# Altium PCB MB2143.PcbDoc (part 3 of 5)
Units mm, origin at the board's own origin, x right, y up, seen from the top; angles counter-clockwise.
Board outline 70 x 70 mm, 4 copper layers (Top Layer, Signal Layer 1, Signal Layer 2, Bottom Layer), stack 1.56 mm thick; 272 components, 188 nets, 1083 pads, 1158 vias.
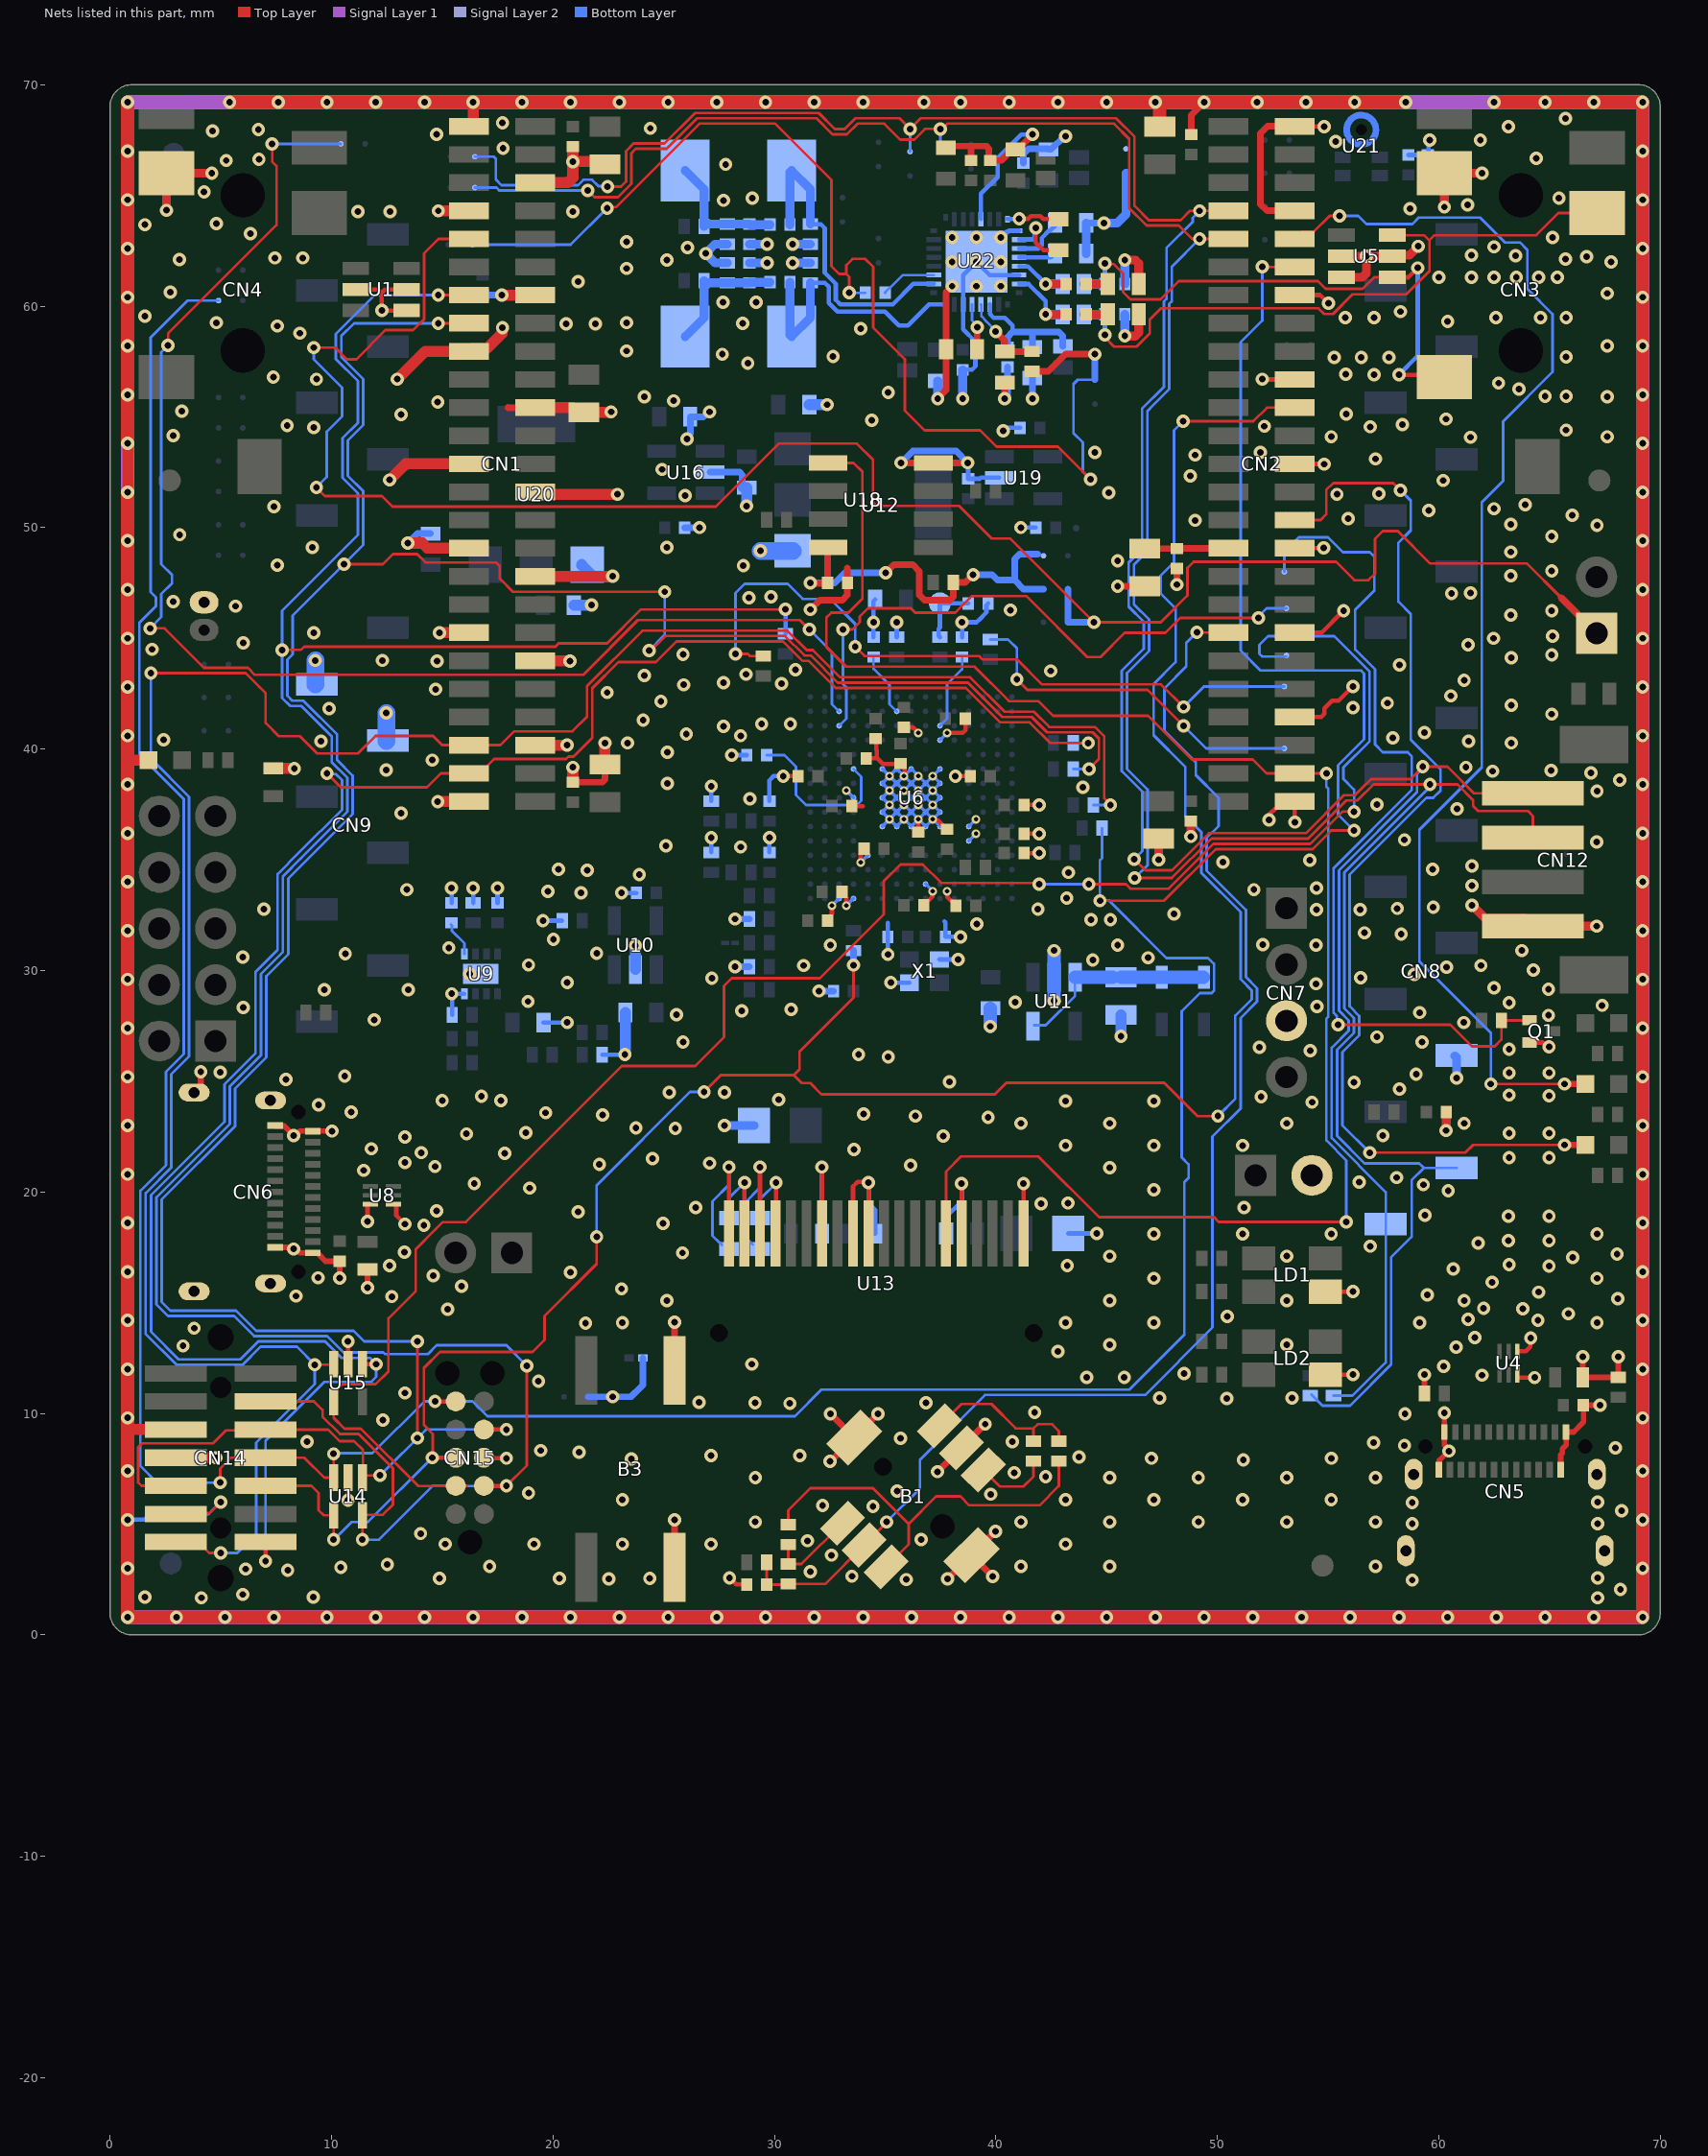
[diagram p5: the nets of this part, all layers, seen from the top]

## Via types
v1: diameter 0.6, hole 0.3, Top Layer to Bottom Layer, 1107 vias
v2: diameter 0.4, hole 0.2, Top Layer to Bottom Layer, tented both sides, 50 vias
v3: diameter 0.6, hole 0.3, Top Layer to Bottom Layer, tented both sides, 1 vias

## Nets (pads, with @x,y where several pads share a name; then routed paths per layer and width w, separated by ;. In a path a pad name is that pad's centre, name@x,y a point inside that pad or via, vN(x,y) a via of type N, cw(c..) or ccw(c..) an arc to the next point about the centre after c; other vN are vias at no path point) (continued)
GND: B1.5 B1.7 B1.8 B3.3 B3.4 C1.2 C2.1 C3.1 C4.1 C5.1 C6.1 C7.1 C8.2 C9.1 C10.1 C11.1 C13.1 C14.1 C15.1 C33.1 C34.2 C35.2 C36.1 C37.2 C38.2 C39.1 C40.2 C41.1 C42.1 C43.1 C44.1 C45.1 C46.1 C47.1 C48.1 C49.1 C50.2 C51.2 C52.2 C53.2 C54.2 C55.2 C56.2 C57.2 C58.2 C59.1 C60.1 C61.2 C62.2 C63.2 C64.2 C65.2 C66.2 C67.2 C68.2 C69.2 C70.1 C73.2 C74.2 C75.2 C76.2 C77.2 C78.2 C79.2 C80.1 C81.1 C82.1 C83.1 C84.1 C85.1 C86.1 C89.1 C90.1 C93.1 C94.1 C95.2 CN1.1 CN1.6 CN1.7 CN1.14 CN1.17 CN1.22 CN1.25 CN1.28 CN1.31 CN1.34 CN1.37 CN1.40 CN1.46 CN1.49 CN2.2 CN2.8 CN2.14 CN2.20 CN2.26 CN2.32 CN2.38 CN2.44 CN2.50 CN5.A1 CN5.A12 CN5.B1 CN5.B12 CN5.SH1 CN5.SH2 CN5.SH3 CN5.SH4 CN6.A1 CN6.A12 CN6.B1 CN6.B12 CN6.SH1 CN6.SH2 CN6.SH3 CN6.SH4 CN7.3 CN8.7 CN9.6 CN9.7 CN12.4 CN14.5 CN14.7 CN15.3 CN16.2 JP1.2 LD1.3 LD2.3 LD4.2 Q1.2 R6.1 R7.1 R11.2 R15.2 R23.2 R25.2 R27.2 R30.1 R33.2 R34.1 R40.1 R46.1 R47.1 SB1.2 SB19.2 U2.2 U3.2 U4.3 U4.4 U6.D5 U6.D6 U6.F6 U6.F7 U6.F8 U6.F9 U6.F10 U6.F12 U6.G2 U6.G6 U6.G7 U6.G8 U6.G9 U6.H6 U6.H7 U6.H8 U6.H9 U6.H10 U6.J6 U6.J7 U6.J8 U6.J9 U6.J10 U6.K6 U6.K7 U6.K8 U6.K9 U6.K10 U6.L4 U6.M1 U6.M8 U6.N1 U7.2 U8.3 U8.4 U9.8 U9.9 U10.2 U11.2 U12.4 U13.7 U13.9 U13.10 U13.16 U13.20 U14.2 U15.2 U16.2 U17.2 U18.1 U19.2 U20.1 U21.3 U22.5 X1.2 X1.4 | length 1365.4
  Top Layer w0.2: v1(10.75,6.075) U14.2@10.75,7.1 ; U15.2@10.75,12.225 v1(10.75,13.25) ; v1@11.63,18.68 U8.3@11.63,19.375 ; U8.4@12.93,19.375 12.93,18.945 v1(13.325,18.55) ; CN15.3@16.885,8 16.91,7.975 v1(17.9,7.975) ; v1(27.975,2.575) 28.275,2.275 C13.1@28.75,2.275 ; v1@30.425,38.75 30.45,38.775 C52.2@31.075,38.775 ; U13.7@32.15,18.125 v1(32.15,21.125) ; C67.2@32.4,32.35 32.4,32.375 32.6,32.575 v2(32.6,32.925) ; C66.2@33.05,33.5 33.05,33.475 33.25,33.275 v2@33.25,32.95 ; C50.2@33.5,37.425 34,37.425 ; U13.9@33.55,18.125 33.55,20.25 33.75,20.45 34.25,20.45 v1@34.275,20.425 ; v2(33.9,34.875) 33.9,35.3 C65.2@34.05,35.45 ; C53.2@34.15,39.58 34.151,39.581 34.625,39.581 ; U13.10@34.25,18.125 v1(34.25,20.425) ; C54.2@34.6,40.375 34.6,39.975 34.625,39.95 34.625,39.581 ; C55.2@35.85,40.975 36.264,40.975 36.514,40.725 v2@36.55,40.725 ; v2@35.875,38.725 35.875,39.1 35.83,39.145 35.83,39.17 35.675,39.325 34.9,39.325 34.644,39.581 34.625,39.581 ; v2@36.45,36.75 36.483,36.75 36.5,36.733 C64.2@36.5,36.25 ; C95.2@36.75,32.95 36.75,32.975 36.905,33.13 36.93,33.13 37.126,33.326 37.126,33.551 v2(37.15,33.575) ; v2(37.15,36.825) 37.187,36.788 37.387,36.788 37.62,36.555 37.62,36.53 37.775,36.375 C63.2@37.8,36.375 ; v2@37.725,33.6 37.812,33.513 37.812,33.313 38.02,33.105 38.045,33.105 38.2,32.95 C68.2@38.2,32.925 ; v2@37.825,40.7 37.85,40.725 38.5,40.725 38.625,40.85 C56.2@38.625,41.375 ; v3@38.35,38.725 38.4,38.775 C57.2@38.85,38.775 ; U13.16@38.45,18.125 v1(38.45,20.375) ; U13.20@41.25,18.125 v1(41.25,20.375) ; C62.2@41.275,35.3 41.925,35.3 v1@42,35.225 ; C61.2@41.275,36.175 41.925,36.175 v1@42,36.1 ; C58.2@41.275,37.475 v1(41.95,37.475) v1@42.025,37.4 ; v1(52.025,56.7) 52.04,56.685 CN2.20@53.5,56.685 ; v1(52.327,36.802) 52.327,37.027 52.66,37.36 53.225,37.36 CN2.50@53.5,37.635 ; CN2.50@53.48,37.635 53.5,37.615 v1(53.5,36.7) ; CN2.38@53.5,45.255 53.505,45.25 54.7,45.25 v1(55.7,46.25) ; CN2.32@53.5,49.065 53.51,49.075 v1(54.8,49.075) ; CN2.14@53.5,60.495 53.505,60.5 54.642,60.5 55.017,60.125 v1(55.025,60.125) ; CN2.2@53.5,68.115 53.504,68.111 54.809,68.111 v1(54.82,68.1) ; CN2.26@53.504,52.875 v1@54.809,52.875 ; CN2.44@53.731,41.676 CN2.44@53.5,41.445 54.695,41.445 54.841,41.591 54.841,41.841 55.175,42.175 55.475,42.175 v1(56.125,42.825) ; LD2.3@54.875,11.75 v1(56.125,11.75) ; LD1.3@54.875,15.5 v1(56.125,15.5) ; U4.3@63.628,11.625 64.32,11.625 v1(64.325,11.62) ; U4.4@63.65,12.812 63.937,12.812 64.13,13.005 64.13,13.38 v1(64.15,13.4) ; Q1.2@64.1,26.75 64.681,26.75 64.881,26.55 v1(64.975,26.55)
  Top Layer w0.25: CN6.B1@7.46,17.5 8.13,17.5 8.205,17.425 v1(8.3,17.425) 8.395,17.425 8.57,17.25 CN6.A12@9.16,17.25 9.36,17.25 9.385,17.225 9.735,16.875 C35.2@10.375,16.875 ; CN6.B12@7.46,23 7.485,22.975 7.875,22.975 v1(8.3,22.55) 8.383,22.55 8.583,22.75 CN6.A1@9.16,22.75 v1(10.025,22.75) ; v1(10.375,16.113) C35.2@10.375,16.863 ; v1(11.625,15.675) U7.2@11.625,16.5 U7.2@11.625,16.513 ; v1(11.625,18.675) v1@11.63,18.68 ; R6.1@59.35,10.9 v1(59.35,11.75) ; CN5.B12@60,7.46 60.025,7.485 60.025,7.875 v1(60.45,8.3) 60.45,8.383 60.25,8.583 CN5.A1@60.25,9.16 v1(60.25,10.025) ; CN5.B1@65.5,7.46 65.5,8.13 65.575,8.205 65.575,8.395 65.75,8.57 CN5.A12@65.75,9.16 66.085,9.16 66.537,9.613 66.537,10.375 v1(67.288,10.375) ; v1(66.505,12.555) 66.5,12.55 U2.2@66.5,11.625 R7.1@67.85,11.625 ; R7.1@68.1,11.625 68.1,12.55 v1(68.105,12.555)
  Top Layer w0.3: CN6.SH3@3.8,24.49 3.869,24.49 4.1,24.721 v1(4.1,25.425) ; 17.975,55.425 17.985,55.415 CN1.22@19.21,55.415 ; C8.2@20.9,38.5 22.225,38.5 22.35,38.625 C3.1@22.35,39.3 ; B3.3@25.5,3.05 v1(25.5,5.2) ; B3.4@25.5,11.95 v1(25.5,14.125) ; v1(31.625,46.3) 32.05,46.725 33.075,46.725 33.3,46.95 C70.1@33.3,47.5 33.3,48.175 ; v1(32.525,9.978) 32.525,9.975 B1.7@33.598,8.902 ; v1@32.538,7.841 B1.7@33.598,8.902 ; v1(34.675,9.975) 34.672,9.975 B1.7@33.598,8.902 ; v1(35.725,52.925) 35.73,52.92 U12.4@37.175,52.92 38.72,52.92 v1(38.725,52.925) ; v1(37.365,7.369) 37.369,7.369 B1.5@38.442,8.442 39.515,9.515 v1(39.519,9.515) ; C89.1@37.75,67.15 37.825,67.225 38.787,67.225 ; v1(37.825,2.525) 37.828,2.525 B1.8@38.902,3.598 ; C90.1@38.875,66.575 38.875,67.138 38.787,67.225 ; v1(39.853,2.64) 39.853,2.647 B1.8@38.902,3.598 ; v1(39.978,4.672) 39.975,4.672 B1.8@38.902,3.598 ; v1(41.65,67.75) 41.65,67.732 41.17,67.252 41.17,67.245 41,67.075 C93.1@40.875,67.075 40.75,67.075 40.25,66.575 C94.1@39.75,66.575 39.691,66.634 39.691,67.1 39.566,67.225 38.787,67.225 ; v1(45.5,47.35) C5.1@46.725,47.35 ; v1(48.175,47.425) C10.1@48.175,48.15 ; C9.1@48.815,67.745 48.815,68.615 v1(49.4,69.2) ; CN2.8@53.5,64.305 52.245,64.305 51.95,64.6 51.95,67.8 52.265,68.115 CN2.2@53.5,68.115
  Top Layer w0.4: v1(47.35,35) C6.1@47.35,35.95 ; v1(48.8,36.05) C11.1@48.8,36.75 ; v1(60.325,22.775) 60.34,22.79 C69.2@60.34,23.602 ; v1(61.5,32.95) 62.1,32.35 63.9,32.35 CN12.4@64.25,32 v1(67.125,32)
  Top Layer w0.5: 0.75,39.525 0.775,39.5 0.8,39.5 LD4.2@1.75,39.5 ; v1(0.8,9.8) 0.8,9.27 CN14.5@2.968,9.27 ; 0.8,36.975 0.825,37 ; v1(0.8,51.6) v1(0.8,53.8) ; CN14.7@2.968,8 v1(4.783,8) ; U17.2@7.375,39.125 v1(8.325,39.125) ; v1(12.625,52.15) 13.35,52.875 CN1.25@16.21,52.875 ; v1(12.975,56.7) 14.23,57.955 CN1.17@16.21,57.955 16.335,58.08 17.022,58.08 17.706,58.764 17.706,59.006 v1(17.725,59.025) ; v1@13.477,49.3 14.1,49.3 14.335,49.065 CN1.31@16.21,49.065 ; v1(14.8,37.625) 14.81,37.635 CN1.49@16.21,37.635 ; v1(14.825,64.3) 14.83,64.305 CN1.7@16.21,64.305 ; v1(14.875,45.25) 14.88,45.255 CN1.37@16.21,45.255 ; CN1.1@16.21,68.115 16.275,68.115 16.4,68.24 v1(16.4,69.2) 16.4,69.225 v1@16.425,69.25 ; v1(17.7,60.5) 17.705,60.495 CN1.14@19.21,60.495 ; CN1.34@19.186,47.795 CN1.34@19.21,47.795 22.695,47.795 v1(22.7,47.8) ; CN1.46@19.21,40.175 v1(20.645,40.175) ; CN1.40@19.21,43.985 20.765,43.985 v1(20.775,43.975) ; CN1.28@19.21,51.605 19.86,51.5 v1(22.923,51.5) ; CN1.22@19.21,55.415 20.935,55.415 21.15,55.2 C1.2@21.4,55.2 22.573,55.2 22.598,55.225 v1(22.625,55.225) ; CN1.6@19.21,65.575 20.675,65.575 20.9,65.8 v1@20.9,66.475 ; C8.2@20.9,38.5 v1(20.9,39.175) ; C7.1@20.9,67.2 v1(20.9,66.525) 22.225,66.525 C2.1@22.35,66.4 ; C3.1@22.35,39.3 v1(22.35,40.275)
  Top Layer w0.6: v1(0.8,51.6) v1(0.8,42.8) v1(0.8,40.6) 0.8,39.5 v1(0.8,29.6) v1(0.8,27.4) v1(0.8,18.6) v1(0.8,16.4) v1(0.8,7.4) v1(0.8,5.2) v1(0.8,0.8) v1(3,0.8) v1(5.2,0.8) v1(7.4,0.8) v1(16.4,0.8) v1(18.6,0.8) v1(27.4,0.8) v1(29.6,0.8) v1(40.6,0.8) v1(42.8,0.8) v1(51.6,0.8) v1(53.8,0.8) v1(62.6,0.8) v1(64.8,0.8) v1(69.2,0.8) v1(69.2,5.2) v1(69.2,7.4) v1(69.2,16.4) v1(69.2,18.6) v1(69.2,27.4) v1(69.2,29.6) v1(69.2,40.6) v1(69.2,42.8) v1(69.2,51.6) v1(69.2,53.8) v1(69.2,62.6) v1(69.2,64.8) v1(69.2,69.2) v1(67,69.2) v1(64.8,69.2) v1(62.5,69.2) ; v1(0.8,53.8) v1(0.8,62.6) v1(0.8,64.8) v1(0.8,69.2) ; v1(5.4,69.2) v1(7.6,69.2) v1(14.2,69.2) v1(16.4,69.2) v1(23,69.2) v1(25.2,69.2) v1(34,69.2) 36.2,69.2 v1(42.8,69.2) v1(45,69.2) v1(51.8,69.2) v1(54,69.2) v1(58.5,69.2) ; v1(47.2,69.2) 47.4,69 C4.1@47.4,68.1
  Signal Layer 1 w0.6: v1(58.5,69.2) v1(62.5,69.2) v1(64.8,69.2) v1(67,69.2) v1(69.2,69.2) v1(69.2,64.8) v1(69.2,62.6) v1(69.2,53.8) v1(69.2,51.6) v1(69.2,42.8) v1(69.2,40.6) v1(69.2,29.6) v1(69.2,27.4) v1(69.2,18.6) v1(69.2,16.4) v1(69.2,7.4) v1(69.2,5.2) v1(69.2,0.8) v1(64.8,0.8) v1(62.6,0.8) v1(53.8,0.8) v1(51.6,0.8) v1(42.8,0.8) v1(40.6,0.8) v1(29.6,0.8) v1(27.4,0.8) v1(18.6,0.8) v1(16.4,0.8) v1(7.4,0.8) v1(5.2,0.8) v1(0.8,0.8) v1(0.8,5.2) v1(0.8,7.4) v1(0.8,16.4) v1(0.8,18.6) v1(0.8,27.4) v1(0.8,29.6) v1(0.8,40.6) v1(0.8,42.8) v1(0.8,51.6) v1(0.8,53.8) v1(0.8,62.6) v1(0.8,64.8) v1(0.8,69.2) v1(5.4,69.2) v1(7.6,69.2) v1(14.2,69.2) v1(16.4,69.2) v1(23,69.2) v1(25.2,69.2) v1(34,69.2) 36.2,69.2 v1(42.8,69.2) v1(45,69.2) v1(51.8,69.2) v1(54,69.2) v1(56.2,69.2) v1(58.5,69.2)
  Signal Layer 2 w0.6: v1(58.5,69.2) v1(62.5,69.2) v1(64.8,69.2) v1(67,69.2) v1(69.2,69.2) v1(69.2,64.8) v1(69.2,62.6) v1(69.2,53.8) v1(69.2,51.6) v1(69.2,42.8) v1(69.2,40.6) v1(69.2,29.6) v1(69.2,27.4) v1(69.2,18.6) v1(69.2,16.4) v1(69.2,7.4) v1(69.2,5.2) v1(69.2,0.8) v1(64.8,0.8) v1(62.6,0.8) v1(53.8,0.8) v1(51.6,0.8) v1(42.8,0.8) v1(40.6,0.8) v1(29.6,0.8) v1(27.4,0.8) v1(18.6,0.8) v1(16.4,0.8) v1(7.4,0.8) v1(5.2,0.8) v1(0.8,0.8) v1(0.8,5.2) v1(0.8,7.4) v1(0.8,16.4) v1(0.8,18.6) v1(0.8,27.4) v1(0.8,29.6) v1(0.8,40.6) v1(0.8,42.8) v1(0.8,51.6) v1(0.8,53.8) v1(0.8,62.6) v1(0.8,64.8) v1(0.8,69.2) v1(5.4,69.2) v1(7.6,69.2) v1(14.2,69.2) v1(16.4,69.2) v1(23,69.2) v1(25.2,69.2) v1(34,69.2) 36.2,69.2 v1(42.8,69.2) v1(45,69.2) v1(51.8,69.2) v1(54,69.2) v1(56.2,69.2) v1(58.5,69.2)
  Bottom Layer w0.15: v2(32.6,32.925) U6.N1@32.925,33.25 ; v2(33.25,32.925) U6.M1@33.575,33.25 ; v2(33.25,38.125) U6.M8@33.575,37.8 ; v2(33.9,34.875) U6.L4@34.225,35.2 ; U6.K6@34.875,36.5 v2(35.2,36.825) ; U6.K10@34.875,39.1 v2(35.2,38.775) ; U6.G2@36.825,33.9 v2(37.15,33.575) ; U6.F6@37.475,36.5 v2(37.15,36.825) ; U6.F10@37.475,39.1 v2(37.15,38.775) ; U6.F12@37.475,40.4 v2(37.8,40.725) ; U6.D5@38.775,35.85 v2(39.1,36.175) ; U6.D6@38.775,36.5 v2(39.1,36.825) ; v2(35.2,36.825) U6.J7@35.525,37.15 ; v2(35.2,36.825) U6.J6@35.525,36.5 v2(35.85,36.825) ; v2(35.2,36.825) U6.K7@34.875,37.15 v2(35.2,37.475) ; v2(35.2,37.475) U6.J8@35.525,37.8 ; v2(35.2,37.475) U6.J7@35.525,37.15 ; v2(35.2,37.475) U6.K8@34.875,37.8 v2(35.2,38.125) ; v2(35.2,38.125) U6.J8@35.525,37.8 ; v2(35.2,38.125) U6.K9@34.875,38.45 v2(35.2,38.775) ; v2(35.2,38.125) U6.J9@35.525,38.45 ; v2(35.2,38.775) U6.J9@35.525,38.45 ; v2(35.2,38.775) U6.J10@35.525,39.1 v2(35.85,38.775) ; U6.J7@35.525,37.15 v2(35.85,36.825) ; U6.J7@35.525,37.15 v2(35.85,37.475) ; U6.J8@35.525,37.8 v2(35.85,37.475) ; U6.J8@35.525,37.8 v2(35.85,38.125) ; U6.J9@35.525,38.45 v2(35.85,38.125) ; U6.J9@35.525,38.45 v2(35.85,38.775) ; v2(35.85,36.825) U6.H7@36.175,37.15 ; v2(35.85,36.825) U6.H6@36.175,36.5 v2(36.5,36.825) ; v2(35.85,37.475) U6.H7@36.175,37.15 ; v2(35.85,37.475) U6.H8@36.175,37.8 ; v2(35.85,38.125) U6.H8@36.175,37.8 ; v2(35.85,38.125) U6.H9@36.175,38.45 ; v2(35.85,38.775) U6.H10@36.175,39.1 v2(36.5,38.775) ; v2(35.85,38.775) U6.H9@36.175,38.45 ; U6.H7@36.175,37.15 v2(36.5,36.825) ; U6.H7@36.175,37.15 v2(36.5,37.475) ; U6.H8@36.175,37.8 v2(36.5,38.125) ; U6.H8@36.175,37.8 v2(36.5,37.475) ; U6.H9@36.175,38.45 v2(36.5,38.125) ; U6.H9@36.175,38.45 v2(36.5,38.775) ; v2(36.5,36.825) U6.G6@36.825,36.5 v2(37.15,36.825) ; v2(36.5,36.825) U6.G7@36.825,37.15 ; v2(36.5,37.475) U6.G7@36.825,37.15 ; v2(36.5,37.475) U6.G8@36.825,37.8 ; v2(36.5,38.125) U6.G8@36.825,37.8 ; v2(36.5,38.125) U6.G9@36.825,38.45 ; v2(36.5,38.775) U6.G9@36.825,38.45 ; U6.G7@36.825,37.15 v2(37.15,36.825) ; U6.G7@36.825,37.15 v2(37.15,37.475) ; U6.G8@36.825,37.8 v2(37.15,37.475) ; U6.G8@36.825,37.8 v2(37.15,38.125) ; U6.G9@36.825,38.45 v2(37.15,38.775) ; U6.G9@36.825,38.45 v2(37.15,38.125) ; v2(37.15,36.825) U6.F7@37.475,37.15 v2(37.15,37.475) ; v2(37.15,37.475) U6.F8@37.475,37.8 v2(37.15,38.125) ; v2(37.15,38.125) U6.F9@37.475,38.45 v2(37.15,38.775)
  Bottom Layer w0.2: v1@0.7,5.2 v1(0.8,5.2) 1.575,5.2 1.835,5.46 R47.1@2.518,5.46 ; v1@15.4,28.95 15.45,28.9 R33.2@15.45,27.995 ; C45.1@15.425,33.05 v1(15.425,33.725) ; v1(15.43,28.95) U9.8@16,28.95 ; v1(16.25,29.85) U9.9@16.75,29.85 ; R34.1@16.4,33.05 v1(16.4,33.725) ; C44.1@17.5,33.05 v1(17.5,33.725) ; v1(19.55,32.25) R40.1@20.42,32.25 ; C43.1@19.575,27.645 20.645,27.645 v1(20.65,27.65) ; R30.1@22.225,26.195 23.245,26.195 v1(23.25,26.2) ; v1(23.1,33.5) C46.1@23.775,33.5 ; v1@23.2,26.2 v1@23.275,26.275 ; R11.2@27.15,35.33 v1(27.15,36.005) ; R15.2@27.15,37.65 v1(27.15,38.325) ; v1(28.075,39.725) C48.1@28.75,39.725 ; C37.2@29.775,35.33 v1(29.775,36.005) ; C38.2@29.775,37.65 29.775,38.575 29.975,38.775 v1(30.4,38.775) ; C75.2@32.15,18.125 v1(32.15,21.125) ; v1@34.25,20.4 34.25,19.5 34.55,19.2 C74.2@34.55,18.125 ; C42.1@34.475,45.05 v1(34.475,45.725) 34.475,46.675 C80.1@34.55,46.75 ; v1(35.125,30.725) C40.2@35.125,31.52 35.125,32.15 ; v1(35.255,29.45) X1.2@36.1,29.45 ; R25.2@35.525,45.05 v1(35.525,45.725) ; X1.4@37.45,30.5 37.455,30.495 v1(38.3,30.495) ; 37.675,32.225 37.725,32.175 C39.1@37.725,31.52 v1(38.4,31.52) ; R46.1@37.75,18.125 37.75,18.875 38.45,19.575 v1(38.45,20.375) ; C49.1@38.475,45.05 v1(38.475,45.725) 39.129,45.725 39.277,45.873 39.573,46.169 39.573,46.498 C36.1@39.65,46.575 ; v1(38.725,52.925) 38.75,52.9 C85.1@38.75,52.2 ; C85.1@38.85,52.2 39.275,52.2 39.325,52.25 U19.2@40.15,52.25 ; U22.5@39.325,63.925 39.325,65.075 40.075,65.825 40.075,66.675 41.15,67.75 v1(41.65,67.75) ; v1(40.325,54.375) 40.433,54.375 40.564,54.506 C82.1@41.094,54.506 ; v1(41.125,50) C86.1@41.8,50 ; C76.2@43.275,18.125 v1(44.55,18.125) ; C34.2@58.625,66.825 C33.1@59.5,66.825 59.542,66.868 59.542,67.458 v1(59.585,67.5)
  Bottom Layer w0.3: v1(13.45,49.3) 13.875,49.725 C83.1@14.475,49.725 ; C15.1@16.825,60.5 v1(17.7,60.5) ; SB1.2@21.6,10.75 v1(22.7,10.75) ; v1@22.725,10.75 23.525,10.75 23.951,11.176 24.062,11.288 U3.2@24.062,12.5 ; C79.2@25.95,50 v1(26.625,50) ; v1(26.05,54) 26.05,54.081 26.2,54.231 C77.2@26.2,55 26.802,55 27.027,55.225 v1(27.075,55.225) ; U16.2@27.1,52.5 28.432,52.5 28.555,52.377 C78.2@28.555,51.87 ; v1(28.22,30.175) R27.2@28.875,30.175 ; v1(28.22,32.325) R23.2@28.875,32.325 ; v1(32.02,29.075) C41.1@32.675,29.075 ; v1(35.725,52.925) 36.25,53.45 38.2,53.45 v1(38.725,52.925)
  Bottom Layer w0.4: v1(27.75,23) C73.2@29.075,23 ; CN8.7@60.73,26.142 60.8,26.073 v1(60.8,25.15)
  Bottom Layer w0.5: C84.1@20.95,46.5 v1(21.75,46.5) ; U20.1@21.3,48.325 21.3,48.3 21.8,47.8 v1(22.7,47.8) ; v1@23.275,26.275 C47.1@23.275,28.1 ; U10.2@23.725,30.05 v1(23.725,31.12) ; C78.2@28.555,51.87 28.625,51.8 C78.2@28.75,51.8 v1(28.75,50.975) ; C81.1@31.575,55.55 v1(32.375,55.55) ; v1(45.65,27.025) C59.1@45.65,27.995
  Bottom Layer w0.6: v1(39.75,27.475) C60.1@39.75,28.295 ; v1(42.625,28.625) U11.2@42.625,29.695 v1(42.625,30.9) ; v1(58.5,69.2) v1(62.5,69.2) v1(64.8,69.2) v1(67,69.2) v1(69.2,69.2) v1(69.2,64.8) v1(69.2,62.6) v1(69.2,53.8) v1(69.2,51.6) v1(69.2,42.8) v1(69.2,40.6) v1(69.2,29.6) v1(69.2,27.4) v1(69.2,18.6) v1(69.2,16.4) v1(69.2,7.4) v1(69.2,5.2) v1(69.2,0.8) v1(64.8,0.8) v1(62.6,0.8) v1(53.8,0.8) v1(51.6,0.8) v1(42.8,0.8) v1(40.6,0.8) v1(29.6,0.8) v1(27.4,0.8) v1(18.6,0.8) v1(16.4,0.8) v1(7.4,0.8) v1(5.2,0.8) v1(0.8,0.8) v1(0.8,5.2) v1(0.8,7.4) v1(0.8,16.4) v1(0.8,18.6) v1(0.8,27.4) v1(0.8,29.6) v1(0.8,40.6) v1(0.8,42.8) v1(0.8,51.6) v1(0.8,53.8) v1(0.8,62.6) v1(0.8,64.8) v1(0.8,69.2) v1(5.4,69.2) v1(7.6,69.2) v1(14.2,69.2) v1(16.4,69.2) v1(23,69.2) v1(25.2,69.2) v1(34,69.2) 36.2,69.2 v1(42.8,69.2) v1(45,69.2) v1(51.8,69.2) v1(54,69.2) v1(56.2,69.2) v1(58.5,69.2)
  Bottom Layer w0.8: CN9.7@9.275,42.915 v1(9.275,44) ; CN9.6@12.475,40.37 v1(12.475,41.625) ; v1(29.375,48.95) U18.1@30.825,48.95
  other v1: 9.8,0.8 12,0.8 14.2,0.8 20.8,0.8 23,0.8 25.2,0.8 31.8,0.8 34,0.8 36.2,0.8 38.4,0.8 45,0.8 47.2,0.8 49.4,0.8 56,0.8 58.2,0.8 60.4,0.8 67,0.8 4.125,1.675 67.175,1.675 1.575,1.7 9.175,1.7 6,1.825 68.2,2.05 58.8,2.475 35.95,2.5 22.525,2.525 14.875,2.55 20.3,2.55 24.375,2.55 67.175,2.575 33.5,2.65 31.625,2.85 8.025,2.925 6.125,2.975 0.8,3 69.2,3 10.425,3.05 17.141,3.1 41.141,3.1 45.141,3.1 57.141,3.1 12.525,3.175 32.575,3.6 15.141,4.1 19.141,4.1 23.141,4.1 27.141,4.1 43.141,4.1 31.5,4.25 36.625,4.3 14.025,4.575 58.8,5.025 67.175,5.025 29.141,5.1 41.141,5.1 45.141,5.1 49.141,5.1 53.141,5.1 57.141,5.1 68.25,5.6 34.45,5.8 32.175,5.85 58.8,5.975 67.175,6 23.141,6.1 43.141,6.1 47.141,6.1 51.141,6.1 55.141,6.1 39.775,6.35 18.9,6.4 35.55,6.5 29.141,7.1 45.141,7.1 49.141,7.1 53.141,7.1 57.141,7.1 42.25,7.15 40.825,7.325 32.509,7.841 51.175,7.9 23.55,7.95 47.025,7.975 55.15,7.975 43.75,8.025 27.141,8.1 31.141,8.1 21.175,8.25 19.45,8.325 67.975,8.45 58.45,8.55 57.05,8.675 8.9,8.725 40.75,8.725 35.7,8.875 12.325,9.7 69.2,9.8 58.475,9.975 41.75,10.05 30.7,10.45 29.125,10.475 36.85,10.475 26.6,10.5 50.425,10.675 47.4,10.7 53.375,10.7 13.325,10.925 19.35,11.45 44.1,11.625 45.8,11.625 61.95,11.725 48.5,11.8 0.8,12 69.2,12 60.225,12.125 28.975,12.225 42.8,12.8 60.775,13 3.3,13.05 45.141,13.1 53.141,13.1 61.625,13.425 3.8,13.85 21.475,14.075 23.141,14.1 43.141,14.1 47.141,14.1 59.141,14.1 67.141,14.1 0.8,14.2 64.475,14.2 69.2,14.2 61.325,14.25 50.45,14.375 65.85,14.5 15.25,14.7 63.8,14.725 62.025,14.75 25.141,15.1 45.141,15.1 53.141,15.1 61.141,15.1 68.075,15.175 12.725,15.275 8.4,15.3 59.475,15.35 64.5,15.475 23.1,15.625 15.875,15.75 62.4,15.925 47.141,16.1 67.141,16.1 9.4,16.125 14.6,16.225 20.8,16.375 60.65,16.525 64.975,16.65 12.625,16.675 43.225,16.675 63.175,16.725 66.05,17.05 45.141,17.1 53.141,17.1 68.05,17.2 25.85,17.25 13.3,17.275 56.9,17.55 61.775,17.7 63.15,17.8 64.975,17.8 47.141,18.1 51.141,18.1 55.141,18.1 67.141,18.1 14.175,18.5 24.975,18.575 63.15,18.9 64.975,18.9 59.375,18.95 21.141,19.1 14.75,19.15 26.45,19.3 51.2,19.3 42.05,19.475 43.25,19.5 60.425,20.05 47.141,20.1 18.95,20.175 59.3,20.325 16.45,20.375 56.4,20.45 58.1,20.65 0.8,20.8 69.2,20.8 11.45,20.975 45.141,21.1 14.675,21.15 36.15,21.2 22.1,21.25 27.075,21.3 13.325,21.325 24.5,21.5 63.175,21.55 64.975,21.55 17.825,21.75 14.05,21.775 33.6,21.925 11.8,21.95 43.141,22.1 47.141,22.1 51.141,22.1 13.325,22.475 37.625,22.525 57.475,22.55 16.1,22.625 63.175,22.65 64.975,22.65 18.775,22.675 25.525,22.875 23.75,22.9 0.8,23 69.2,23 41.141,23.1 45.141,23.1 53.141,23.1 61.141,23.1 39.65,23.375 36.375,23.425 22.25,23.475 34.025,23.525 19.675,23.575 10.9,23.6 9.425,23.925 54.275,24.05 43.141,24.1 47.141,24.1 15,24.125 17.65,24.125 30.2,24.175 51.975,24.3 16.775,24.325 64.975,24.35 63.175,24.375 25.25,24.5 27.75,24.5 58.225,24.65 56.175,24.95 37.9,24.975 7.95,25.075 0.8,25.2 69.2,25.2 10.6,25.225 58.975,25.325 63.175,25.375 64.975,25.375 4.975,25.4 35.141,26.1 33.8,26.2 54.2,26.375 63.175,26.45 51.9,26.525 25.875,26.775 59.25,26.775 57.2,27 61.125,27.65 11.925,27.775 64.95,27.975 25.575,28 59.141,28.1 28.525,28.175 30.75,28.25 6.025,28.325 54.5,28.375 67.375,28.425 63.175,28.55 40.875,28.575 18.875,28.6 9.675,29.125 13.475,29.125 64.95,29.15 62.5,29.225 54.45,29.4 20.65,29.45 27.175,29.65 56.475,29.675 58.9,29.825 64.275,30.025 60.35,30.15 31.325,30.225 61.9,30.225 18.9,30.25 44.375,30.475 46.875,30.575 6,30.6 10.625,30.75 21.975,30.775 63.75,30.9 15.3,31.025 32.525,31.15 45.5,31.15 54.45,31.15 52.05,31.175 20.025,31.4 58.3,31.65 56.65,31.7 0.8,31.8 69.2,31.8 39.141,32.1 44.3,32.3 45.175,32.3 48.05,32.55 54.475,32.75 56.45,32.75 6.95,32.775 41.9,32.775 58.125,32.8 59.75,32.85 43.2,33.275 21.275,33.5 19.775,33.575 13.4,33.65 51.65,33.65 54.475,33.725 61.5,33.825 0.8,34 69.2,34 23.9,34.325 43.275,34.425 21.55,34.525 20.25,34.575 59.725,34.575 61.5,34.725 50.25,34.9 54.175,34.975 41.95,35.3 28.475,35.575 25.1,35.625 67.125,35.8 58.45,35.9 41.95,36.175 0.8,36.2 69.2,36.2 13.141,37.1 60.825,37.3 57.2,37.5 28.9,37.75 67.141,38.1 43.925,38.275 0.8,38.4 69.2,38.4 25.175,38.45 68.175,38.6 66.875,38.925 62.425,39 65.075,39.025 12.475,39.05 61.225,39.175 14.55,39.5 25.175,39.85 23.375,40.275 63.275,40.275 9.525,40.35 61.35,40.35 2.425,40.425 57.925,40.5 28.475,40.6 26.025,40.675 59.35,40.75 27.7,41.025 29.425,41.125 30.725,41.125 24.075,41.3 65.1,41.575 9.9,41.825 56.125,41.875 63.275,41.975 57.675,42.075 24.875,42.15 60.55,42.4 22.45,42.55 14.7,42.7 25.9,42.9 30.325,42.95 27.7,43 61.141,43.1 24.125,43.325 28.725,43.375 42.475,43.525 30.95,43.575 58.225,43.8 14.775,43.975 12.3,44 63.275,44.125 65.1,44.25 25.875,44.275 1.9,44.5 61.325,44.7 6.025,44.8 0.8,45 62.475,45 69.2,45 65.141,45.1 9.2,45.25 63.25,46.05 65.1,46.25 40.65,46.275 5.675,46.45 2.85,46.65 28.85,46.825 29.85,46.875 60.575,47.025 61.425,47.05 0.8,47.2 69.2,47.2 63.25,47.825 65.1,48.05 28.6,48.275 7.55,48.3 45.5,48.5 63.25,48.9 9.141,49.1 25.141,49.1 0.8,49.4 69.2,49.4 65.1,49.6 3.15,49.675 67.141,50.1 63.25,50.15 49,50.325 55.9,50.4 66.025,50.55 59.55,50.775 62.5,50.85 7.4,50.95 63.9,51.025 25.975,51.45 55.4,51.5 57.3,51.525 45.1,51.575 60.2,52.125 48.775,52.325 24.925,52.625 54.82,52.864 57.141,53.1 49,53.275 44.475,53.4 51.95,53.4 61.425,54.075 55.141,54.1 67.6,54.1 2.85,54.15 65.75,54.4 9.2,54.525 52.125,54.575 56.9,54.55 8,54.6 58.35,54.65 34.4,54.85 60.325,54.9 13.141,55.1 55.825,55.125 3.25,55.25 14.8,55.675 25.45,55.725 24.125,55.9 67.6,55.9 64.8,55.925 65.75,55.925 0.8,56 69.2,56 35.141,56.1 63.625,56.25 62.7,56.525 9.325,56.7 7.375,56.8 57.075,56.9 55.8,56.925 28.8,57.425 55.275,57.675 56.5,57.675 57.75,57.675 65.75,57.7 32.65,57.725 27.65,57.825 23.325,57.975 0.8,58.2 67.6,58.2 69.2,58.2 8.575,58.775 33.9,58.975 7.55,59.1 20.6,59.2 21.925,59.2 28.575,59.225 4.8,59.25 23.325,59.25 60.4,59.3 55.775,59.475 57.075,59.475 62.575,59.475 64.6,59.475 65.75,59.475 1.575,59.55 58.275,59.75 27.675,60.175 29.175,60.175 0.8,60.4 69.2,60.4 67.6,60.575 2.725,60.625 21.141,61.1 60,61.3 61.475,61.3 62.5,61.3 63.5,61.3 64.5,61.3 65.35,61.3 23.325,61.7 67.775,62 25.15,62.075 3.141,62.1 65.725,62.125 7.45,62.175 8.7,62.175 66.675,62.225 63.475,62.275 61.475,62.3 26.075,62.65 62.5,62.675 23.325,62.9 65.141,63.1 6.35,63.275 1.575,63.675 4.8,63.725 11.2,64.275 12.65,64.275 20.9,64.275 58.7,64.4 61.3,64.575 27.7,64.775 29,64.875 65.425,64.875 4.25,65.15 27.8,66.4 5.25,66.575 6.725,66.625 64.4,66.675 0.8,67 69.2,67 17.75,67.125 55.35,67.425 61.875,67.5 14.75,67.75 4.625,67.9 6.7,67.975 24.4,68.025 63.141,68.1 17.725,68.275 65.725,68.475 9.8,69.2 12,69.2 18.6,69.2 20.8,69.2 27.4,69.2 29.6,69.2 31.8,69.2 36.75,69.2 38.4,69.2 40.6,69.2
  other v2: 37.8,33.575 36.5,40.725
  other v3: 38.175,38.775
GND_Audio: C18.1 C19.2 C20.1 C21.2 C22.2 C24.2 C27.1 C29.1 C30.1 C31.1 C32.1 C87.1 C91.1 C92.1 CN3.3 CN4.3 R10.2 R49.1 R50.1 R51.1 R52.2 R55.1 SB19.1 U1.2 U1.4 U1.5 U5.2 U5.3 U5.5 U22.9 U22.14 U22.22 U22.33 | length 55.1
  Top Layer w0.2: U1.2@11.1,60.75 12.1,60.75 12.275,60.575 ; v1@12.225,59.8 12.275,59.85 12.275,60.575 ; v1(12.275,59.8) U1.4@13.4,59.8 ; U1.5@13.4,60.75 12.425,60.75 12.275,60.6 12.275,60.575
  Top Layer w0.3: v1(37.375,55.825) 37.75,56.2 C27.1@37.75,58.05 37.75,60.625 v1(38.025,60.9) ; v1(40.4,55.825) C19.2@40.4,56.55
  Top Layer w0.4: v1(2.55,64.325) CN4.3@2.55,66 v1(4.6,66) ; v1(45.825,58.65) 46.298,58.65 46.45,58.802 R50.1@46.45,59.625 ; v1(45.825,62.075) 46.298,62.075 46.45,61.923 R49.1@46.45,61 ; U5.3@55.6,61.3 56.55,61.3 56.73,61.48 v1(56.73,62.25) ; U5.2@55.6,62.25 v1(56.73,62.25) ; v1(59.075,62.7) 58.668,62.293 57.943,62.293 U5.5@57.9,62.25 v1(56.73,62.25) ; v1(60.25,64.475) CN3.3@60.25,66 v1(61.95,66)
  Bottom Layer w0.2: C20.1@38.5,57.125 38.925,57.125 39.075,57.275 39.075,58.398 38.525,58.948 U22.22@38.525,60.075 38.525,61.4 v1(39.125,62) 39.725,61.4 U22.14@41.05,61.4 ; v1(40.225,63.1) 40.5,63.375 U22.33@40.5,63.376 ; U22.33@40.491,63.3 40.591,63.4 U22.9@41.05,63.4
  Bottom Layer w0.3: v1(40.4,55.825) 40.402,55.825 40.525,55.948 C87.1@40.525,57.25 ; C92.1@41.25,66.45 41.25,66.875 41.475,67.1 42.35,67.1 C91.1@42.375,67.075 42.5,67.075 43.1,67.675 v1(43.15,67.675) ; v1(41.65,55.825) C32.1@41.65,56.75 ; C21.2@44.075,63.75 v1(44.875,63.75)
  Bottom Layer w0.4: R52.2@27.875,61.95 27.325,61.95 v1(26.9,62.375) 27.325,62.8 R51.1@27.875,62.8 ; C24.2@28.875,61.95 v1(29.675,61.95) ; C18.1@28.875,62.8 v1(29.675,62.8) ; v1(30.825,61.95) R55.1@31.625,61.95 ; v1(30.825,62.8) R10.2@31.625,62.8 ; v1(37.375,55.825) C31.1@37.375,56.625 ; v1(38.5,55.825) C20.1@38.5,57.125 ; C22.2@44.075,62.375 C21.2@44.075,63.75 ; v1(44.875,63.75) 45.475,63.75 45.875,64.15 SB19.1@45.875,66 ; v1(45.825,58.65) C29.1@45.825,59.625 ; C30.1@45.825,61 v1(45.825,62.075)
  other v1: 39.125,60.9 40.225,60.9 38.025,62 40.225,62 38.025,63.1 39.125,63.1
GNDDetect: CN14.11 R47.2 | length 4
  Top Layer w0.12: CN14.11@2.968,5.46 3.003,5.495 4.495,5.495 v1(5,6)
  Bottom Layer w0.12: R47.2@3.418,5.46 4.454,5.46 4.654,5.66 4.66,5.66 v1@4.975,5.975
GPIO30: CN2.10 LD6.2 | length 58
  Top Layer w0.12: CN2.10@53.5,63.035 53.815,63.35 54.35,63.35 55.075,64.075 v1(55.525,64.075) ; v1(62.35,24.875) v1(65.675,24.875)
  Top Layer w0.3: v1(65.675,24.875) LD6.2@66.625,24.875
  Bottom Layer w0.12: v1(55.525,64.075) 56.361,64.075 56.726,63.71 58.81,63.71 59.095,63.995 61.859,63.995 62.98,62.874 63.655,62.874 64,62.529 64,60.775 65.135,59.64 65.135,57.025 62.901,54.791 62.901,52.105 61.941,51.145 61.941,39.173 59.125,36.357 59.125,30.41 62.35,27.185 v1(62.35,24.875)
GPIO45: CN2.30 LD5.2 | length 50.2
  Top Layer w0.12: CN2.30@53.5,50.335 54.66,50.335 54.918,50.593 54.918,51.697 55.231,52.01 57.94,52.01 v1(58.275,51.675) ; v1(56.875,21.775) 61.2,21.775 61.55,22.125 v1(65.675,22.125)
  Top Layer w0.3: v1(65.675,22.125) LD5.2@66.625,22.125
  Bottom Layer w0.12: v1(56.875,21.775) 55.645,23.005 55.645,26.316 56.41,27.081 56.41,27.948 55.97,28.388 55.97,34.327 59.443,37.8 59.75,37.8 60.08,38.13 60.08,39.074 58.736,40.418 58.736,46.1 58.175,46.661 58.175,49.314 58.736,49.875 58.736,51.214 v1(58.275,51.675)
I2C1_SCL: CN2.7 CN8.10 CN12.1 R8.1 SB16.2 SB29.2 | length 128.8
  Top Layer w0.12: v1(22.469,65.4) 23.075,65.4 23.3,65.625 23.3,67 23.64,67.34 25.036,67.34 26.416,68.72 32.001,68.72 32.726,67.995 33.174,67.995 33.659,68.48 35.645,68.48 v1(36.125,68) 36.605,68.48 42.502,68.48 45.431,68.48 46.26,67.651 46.26,64.526 46.906,63.88 48.345,63.88 48.77,64.305 CN2.7@50.5,64.305 ; v1(46.25,35.025) 46.755,34.52 47.949,34.52 49.629,36.2 54,36.2 55.715,37.915 56.215,37.915 56.7,38.4 56.711,38.4 56.951,38.64 58.715,38.64 v1(59.275,39.2) 60.385,39.2 61.585,38 CN12.1@64.25,38
  Bottom Layer w0.12: SB29.2@16.475,66.75 17.325,66.75 17.425,66.65 17.425,65.714 17.674,65.465 21.136,65.465 21.376,65.705 21.774,65.705 22.059,65.42 22.449,65.42 v1(22.469,65.4) ; SB16.2@36.125,66.975 v1(36.125,68) ; v1(46.25,35.025) 46.615,35.39 46.615,38.071 45.685,39.001 45.685,43.535 46.675,44.525 46.675,45.749 45.995,46.429 45.995,48.421 46.6,49.026 46.6,55.361 47.59,56.351 47.59,60.208 47.705,60.323 47.705,62.616 48.89,63.801 48.89,63.99 v1(49.2,64.3) ; R8.1@55.25,10.8 56.1,10.8 57.603,12.304 CN8.10@57.603,18.543 57.603,19.997 55.165,22.435 55.165,26.515 55.93,27.28 55.93,27.749 55.49,28.189 55.49,34.526 59.015,38.051 59.015,38.89 59.275,39.15 v1(59.275,39.2)
I2C1_SDA: CN2.9 CN8.9 CN12.2 R9.1 SB17.2 SB27.2 | length 133.5
  Top Layer w0.12: v1(21.575,65.225) 21.88,64.92 22.934,64.92 23.174,65.16 23.54,65.526 23.54,66.901 23.739,67.1 25.136,67.1 26.516,68.48 31.902,68.48 32.627,67.755 33.273,67.755 33.758,68.24 34.96,68.24 35.68,67.52 36.324,67.52 36.804,68 v1(37.5,68) 37.57,68 37.81,68.24 42.402,68.24 45.331,68.24 46.02,67.551 46.02,64.426 46.806,63.64 48.26,63.64 48.865,63.035 CN2.9@50.5,63.035 ; v1(46.275,34.175) 47.943,34.175 49.728,35.96 54.099,35.96 55.814,37.675 56.325,37.675 57.05,38.4 v1(59.6,38.4) 60.845,38.4 61.55,37.695 61.55,37.425 61.775,37.2 64.025,37.2 64.25,36.975 CN12.2@64.25,36
  Bottom Layer w0.12: SB27.2@16.475,65.35 17.45,65.35 17.575,65.225 v1(21.575,65.225) ; SB17.2@37.5,66.975 v1(37.5,68) ; v1(46.275,34.175) 46.855,34.755 46.855,38.171 45.925,39.101 45.925,43.436 46.915,44.426 46.915,45.849 46.235,46.529 46.235,48.321 46.84,48.926 46.84,55.261 47.114,55.536 47.83,56.251 47.83,60.109 47.945,60.224 47.945,61.775 v1(49.2,63.03) ; R9.1@54.25,10.85 54.75,10.35 55.989,10.35 57.843,12.204 57.843,17.043 58.775,17.975 58.775,20.535 59.323,21.083 ; v1(59.6,38.4) 59.6,38.296 55.73,34.426 55.73,28.288 56.17,27.848 56.17,27.181 55.405,26.416 55.405,22.534 56.647,21.292 59.114,21.292 59.323,21.083 ; CN8.9@60.808,21.083 59.323,21.083
IN2L: C12.2 C16.2 R10.1 U22.26 | length 14.4
  Bottom Layer w0.2: C12.2@30.7,63.675 C12.2@30.775,63.75 ; R10.1@31.625,63.7 32.1,63.7 32.275,63.525 32.275,61.503 32.77,61.008 32.77,60.283 32.978,60.075 35.35,60.075 36.275,61 U22.26@37.2,61
  Bottom Layer w0.4: C12.2@30.7,63.675 30.7,66.05 C16.2@30.775,66.125 31.625,65.275 R10.1@31.625,63.7
IN2R: C25.2 C88.2 R55.2 U22.24 | length 13
  Bottom Layer w0.2: R55.2@31.625,61.05 32.275,61.05 32.45,60.875 32.45,60.15 32.845,59.755 34.995,59.755 35.625,59.125 36.027,59.125 36.977,60.075 U22.24@37.725,60.075
  Bottom Layer w0.4: C88.2@30.7,61.075 30.7,58.7 C25.2@30.775,58.625 31.625,59.475 R55.2@31.625,61.05
JNTRST: CN15.9 SB31.1 U15.4 | length 85.5
  Top Layer w0.12: 14.7,18.325 14.7,18.314 13.81,17.424 13.81,15.535 12.575,14.3 12.575,11.9 12,11.325 10.5,11.325 10.24,11.065 10.1,10.925 U15.4@10.1,10.525 U15.4@10.1,10.525 10.101,9.799 10.59,9.31 11.329,9.31 13.914,6.725 16.1,6.725 ; 14.705,18.32 15.026,18.64 16.065,18.64 23.115,25.69 26.426,25.69 27.725,26.989 27.725,29.309 28.066,29.65 32.05,29.65 34.941,32.541 34.941,34.037 35.693,34.789 36.699,34.789 37.533,33.955 41.895,33.955 v1(41.95,33.9) ; v1(44.2,33.9) 45.871,33.9 46.076,33.695 47.803,33.695 49.828,35.72 54.199,35.72 55.654,37.175 v1(56.175,37.175)
  Bottom Layer w0.12: v1(41.95,33.9) v1(44.2,33.9) ; SB31.1@53.125,44.175 52.025,44.175 51.9,44.3 51.9,44.713 52.288,45.1 55.275,45.1 56.875,43.5 56.875,40.35 55.695,39.17 55.695,38.651 56.175,38.171 v1(56.175,37.175)
LEDU: Q1.1 R42.2 SB2.2 | length 40.4
  Top Layer w0.12: v1(55.45,27.55) 60.525,27.55 61.5,26.575 62.525,26.575 62.825,26.875 R42.2@62.825,27.75 Q1.1@64.1,27.75
  Bottom Layer w0.12: SB2.2@53.025,48 53.025,48.9 53.68,49.555 54.999,49.555 55.666,48.888 56.888,48.888 57.088,48.688 57.088,47.163 56.225,46.3 56.225,44.489 57.115,43.599 57.115,40.21 57.475,39.85 58.6,39.85 58.775,39.675 58.775,38.15 55.25,34.625 55.25,28.089 55.4,27.939 55.4,27.6 v1(55.45,27.55)
MCU.CTS: SB40.1 U6.N13 | length 27.6
  Top Layer w0.12: v1(33.1,45.4) 33.525,45.4 33.85,45.725 33.85,45.982 34.218,46.35 36.161,46.35 36.356,46.155 38.161,46.155 38.453,46.447 38.916,46.91 41.372,46.91 44.127,44.155 44.723,44.155 45.813,45.245 47.649,45.245 48.329,45.925 v1(51.85,45.925)
  Bottom Layer w0.12: U6.N13@32.925,41.05 33.25,41.375 33.25,42.787 33.1,42.937 v1(33.1,45.4) ; v1(51.85,45.925) 51.85,45.975 52.225,46.35 SB40.1@53.125,46.35
MCU.JTDI: CN2.22 CN14.10 CN15.8 R19.2 U14.4 | length 108.6
  Top Layer w0.12: CN14.10@7.032,6.73 9.095,6.73 9.425,6.4 9.425,5.625 9.65,5.4 U14.4@10.075,5.4 ; v1(10.1,4.3) U14.4@10.1,5.4 ; v1(14.55,8) 14.575,8.025 14.575,9.075 14.175,9.475 14.175,12.05 14.9,12.775 19.075,12.775 19.625,13.325 19.625,14.4 21.975,16.75 v1(21.975,17.978) ; v1(26.825,24.515) 27.585,25.275 30.875,25.275 ; v1@33.58,30.255 33.575,30.25 v1(33.575,30.245) 33.575,28.775 31.138,26.338 31.138,25.538 30.875,25.275 ; v1(48.45,54.8) 51.625,54.8 52.24,55.415 CN2.22@53.5,55.415 ; v1(50.025,23.425) 49.1,23.425 47.6,24.925 40.475,24.925 39.955,24.405 32.13,24.405 31.616,24.919 31.231,24.919 30.875,25.275
  Top Layer w0.2: v1(14.55,8) CN15.8@15.615,8
  Bottom Layer w0.12: v1@10.125,4.3 10.925,5.1 11.65,5.1 v1(14.55,8) ; v1(21.975,17.978) 21.975,20.3 26.19,24.515 v1(26.825,24.515) ; v1(48.45,54.8) 48.04,54.39 48.04,48.429 47.435,47.824 47.435,47.026 48.115,46.346 48.115,43.929 47.125,42.939 47.125,40.622 48.55,39.197 48.55,36.979 49.28,36.249 49.28,34.406 51.05,32.636 51.05,29.604 51.555,29.099 51.555,28.701 50.81,27.956 50.81,24.21 v1(50.025,23.425)
  Bottom Layer w0.3: v1(33.575,30.245) R19.2@33.575,30.9
MCU.RTS: SB39.1 U6.N14 | length 63.9
  Top Layer w0.12: v1(1.811,45.45) 2.461,45.45 4.246,43.665 6.228,43.665 6.543,43.35 21.364,43.35 23.838,45.823 31.152,45.823 v1(31.575,45.4) ; v1(2.625,58.225) 2.625,58.772 7.52,63.667 7.52,66.33 7.325,66.525 v1(7.325,67.325)
  Bottom Layer w0.12: v1(1.811,45.45) 2.32,45.959 2.32,46.996 2.8,47.476 2.8,47.874 2.32,48.354 2.32,57.92 v1(2.625,58.225) ; v1(7.325,67.325) SB39.1@10.425,67.325 ; v1(31.575,45.4) 32.6,44.375 32.6,42.025 U6.N14@32.925,41.7
MCU.SWCLK: CN1.15 CN14.6 CN14.9 CN15.4 R18.2 U14.1 | length 141
  Top Layer w0.12: CN14.9@2.968,6.73 1.427,6.73 1.28,6.877 1.28,7.599 1.28,8.477 1.453,8.65 4.65,8.65 5.236,9.236 6.998,9.236 CN14.6@7.032,9.27 9.847,9.27 10.367,8.75 11.025,8.75 11.425,8.35 U14.1@11.425,7.15 ; v1(10.575,48.35) 12.317,48.35 12.772,48.805 13.87,48.805 14.25,48.425 17.425,48.425 17.6,48.25 17.6,47.7 18.2,47.1 v1(25.05,47.1) ; U14.1@11.4,7.1 11.5,7.2 v1(12.2,7.2) ; v1(13.875,13.25) 13.887,13.238 v1(13.887,8.888) ; v1(14.825,59.225) CN1.15@16.21,59.225 ; v1(24.35,44.45) 24.43,44.45 25.084,45.103 30.482,45.103 31.362,44.224 31.64,44.224 32.864,43 38.739,43 40.294,41.445 41.623,41.445 42.313,40.755 44.374,40.755 44.655,40.474 44.655,39.55 v1(44.205,39.1)
  Top Layer w0.2: CN15.4@16.885,9.275 v1(17.9,9.275)
  Bottom Layer w0.12: 10.445,57.705 11.437,56.713 11.437,54.627 10.745,53.935 10.745,52.34 11.437,51.648 11.437,49.212 v1(10.575,48.35) 8.255,46.03 8.255,44.276 8.015,44.036 8.015,42.403 8.233,42.185 8.733,42.185 10.257,40.661 10.257,39.499 10.957,38.799 10.957,37.064 8.05,34.157 8.05,30.741 7.055,29.746 7.055,26.073 5.65,24.668 5.65,22.968 2.34,19.658 2.34,15.024 2.724,14.64 5.699,14.64 6.609,13.73 10.995,13.73 11.475,13.25 v1(13.875,13.25) ; 10.45,57.705 10.45,57.963 10.445,57.968 10.445,58.645 11.025,59.225 v1(14.825,59.225) ; v1(12.2,7.2) 14.275,9.275 v1(17.9,9.275) ; v1(24.35,44.45) 25.05,45.15 v1(25.05,47.1) ; R18.2@43.5,39.1 v1(44.205,39.1)
MCU.SWDIO: CN1.13 CN14.4 CN15.2 R16.2 U14.5 | length 126.7
  Top Layer w0.12: CN14.4@7.032,10.54 9.21,10.54 9.6,10.15 9.6,9.857 10.387,9.07 11.23,9.07 12.775,7.525 12.775,5.875 12.325,5.425 U14.5@11.35,5.425 ; v1(7.775,44.475) 8.625,44.475 8.775,44.625 20.11,44.625 20.26,44.775 22.45,44.775 23.978,46.303 v1(30.5,46.303) ; v1(11.4,4.3) U14.5@11.4,5.4 ; v1(14.825,60.5) 14.83,60.495 CN1.13@16.21,60.495 ; v1(17.9,6.725) 18.825,7.65 v1(18.825,12.15)
  Top Layer w0.2: CN15.2@16.885,6.725 v1(17.9,6.725)
  Bottom Layer w0.12: v1(11.4,4.3) 12.15,4.3 14.575,6.725 v1(17.9,6.725) ; v1(14.825,60.5) 11.961,60.5 10.205,58.744 10.205,57.606 11.197,56.614 11.197,54.727 10.505,54.035 10.505,52.24 11.197,51.548 11.197,49.664 7.775,46.242 v1(7.775,44.475) 7.775,42.304 8.134,41.945 8.634,41.945 10.017,40.562 10.017,39.399 10.717,38.699 10.717,37.163 8.636,35.082 7.81,34.256 7.81,30.841 6.815,29.846 6.815,26.173 5.41,24.768 5.41,23.068 2.1,19.758 2.1,14.925 2.625,14.4 5.6,14.4 6.51,13.49 9.81,13.49 10.55,12.75 12.35,12.75 12.425,12.675 14.35,12.675 14.75,13.075 17.9,13.075 v1(18.825,12.15)
  Bottom Layer w0.2: R16.2@30.5,45.2 v1(30.5,46.303)
MCU.SWO: CN2.12 CN14.8 CN15.6 R17.2 SB28.2 U14.3 | length 183.6
  Top Layer w0.12: v1(4.975,6.875) 4.975,7.513 5.131,7.669 5.462,8 CN14.8@7.032,8 8.775,8 9.675,7.1 U14.3@10.1,7.1 v1(10.1,8.175) ; v1(44.7,33.15) 47.597,33.15 49.927,35.48 54.298,35.48 55.143,36.325 v1(56.175,36.325) ; v1(52.025,61.78) 52.04,61.765 CN2.12@53.5,61.765
  Top Layer w0.2: v1(14.675,10.55) 14.685,10.54 CN15.6@15.6,10.54
  Bottom Layer w0.12: SB28.2@4.9,60.25 3.511,60.25 1.84,58.579 1.84,58.225 1.84,47.089 2.08,46.849 2.08,46.451 1.331,45.702 1.331,39.744 3.335,37.74 3.335,26.225 2.53,25.42 2.53,21.206 1.375,20.051 1.375,7.625 2.125,6.875 v1(4.975,6.875) ; v1@10.1,8.2 11.85,8.2 14.2,10.55 v1(14.675,10.55) 16.375,10.55 17.05,9.875 30.925,9.875 32.125,11.075 46.025,11.075 48.51,13.56 48.51,20.439 48.7,20.629 48.7,21.25 48.39,21.56 48.39,28.165 49.21,28.985 49.745,28.985 49.85,29.09 49.85,30.3 49.587,30.563 47.702,30.563 45.115,33.15 v1(44.7,33.15) 44.7,34.975 44.8,35.075 R17.2@44.8,36.425 ; v1(52.025,61.78) 52.025,59.343 51.055,58.373 51.055,44.445 51.955,43.545 56.491,43.545 56.625,43.411 56.625,40.439 55.455,39.269 55.455,37.045 v1(56.175,36.325)
MCU.VCP2_RX: R57.2 SB42.2 | length 16.1
  Top Layer w0.12: v1(40.95,43.15) 41.425,42.675 46.85,42.675 v1(48.475,41.05)
  Bottom Layer w0.12: R57.2@39.75,44.95 40.55,44.95 40.95,44.55 v1(40.95,43.15) ; v1(48.475,41.05) 49.5,40.025 SB42.2@53.025,40.025
MCU.VCP2_TX: R58.2 SB41.2 | length 32.3
  Top Layer w0.12: v1(28.25,44.3) 28.8,44.3 28.9,44.2 R58.2@29.5,44.2 ; v1(33.65,44.625) 34.075,44.2 39.236,44.2 39.386,44.05 40.95,44.05 42.085,42.915 47.46,42.915 v1(48.475,41.9)
  Bottom Layer w0.12: v1(28.25,44.3) 28.25,47.05 28.66,47.46 30.601,47.46 31.281,46.78 32.52,46.78 33.65,45.65 v1(33.65,44.625) ; v1(48.475,41.9) 49.4,42.825 SB41.2@53.025,42.825
MCU.VCP_RX: CN1.45 CN14.13 R21.2 U15.3 | length 108.8
  Top Layer w0.12: v1(1.85,43.425) 6.129,43.425 6.749,42.805 7.03,42.524 7.03,41.17 7.62,40.58 8.567,40.58 9.347,39.8 11.2,39.8 11.99,40.59 14.585,40.59 15,40.175 CN1.45@16.21,40.175 17.625,40.175 18.25,40.8 20.875,40.8 21.54,41.465 21.54,42.847 24.036,45.343 30.582,45.343 31.461,44.464 31.74,44.464 32.964,43.24 38.839,43.24 40.394,41.685 41.723,41.685 42.413,40.995 44.473,40.995 44.895,40.573 44.895,37.774 45.175,37.494 v1(45.175,37.475) ; CN14.13@2.968,4.19 3.993,4.19 4.263,3.92 4.263,3.912 4.475,3.7 v1(5,3.7) ; v1(9.25,12.2) 10.05,12.2 U15.3@10.1,12.25
  Bottom Layer w0.12: v1(1.85,43.425) 1.85,39.564 3.575,37.839 3.575,26.126 2.77,25.321 2.77,21.106 1.615,19.951 1.615,13.585 3,12.2 5.989,12.2 6.799,13.01 8.44,13.01 v1(9.25,12.2) 9.25,11.325 6.6,8.675 6.6,4.55 5.75,3.7 v1(5,3.7) ; R21.2@44.4,37.475 v1(45.175,37.475)
MCU.VCP_TX: CN1.47 CN14.14 R20.2 U15.1 | length 95.8
  Top Layer w0.12: v1(9.8,38.9) 10.425,38.275 14.32,38.275 14.95,38.905 CN1.47@16.21,38.905 16.735,38.905 17.05,39.22 17.05,39.25 17.35,39.55 20.596,39.55 20.701,39.655 20.93,39.655 21,39.725 21,39.73 21.78,40.51 21.78,42.747 22.958,43.925 24.65,43.925 25.588,44.863 30.383,44.863 31.262,43.984 31.541,43.984 32.765,42.76 38.64,42.76 40.195,41.205 41.524,41.205 42.454,40.275 v1(44.175,40.275)
  Top Layer w0.2: v1(7.025,3.325) 7.032,3.332 CN14.14@7.032,4.19 ; U15.1@11.35,12.225 v1(12.025,12.225)
  Bottom Layer w0.12: 1.855,18.75 1.855,13.684 3.099,12.44 5.89,12.44 6.7,13.25 9.711,13.25 10.451,12.51 11.731,12.51 12.016,12.225 v1(12.025,12.225) 12.025,11.65 11.8,11.425 9.689,11.425 7.025,8.761 v1(7.025,3.325) ; 1.86,18.75 1.86,19.857 5.17,23.167 5.17,24.867 6.575,26.272 6.575,29.945 7.57,30.94 7.57,34.355 8.536,35.322 10.477,37.262 10.477,38.6 10.208,38.869 9.831,38.869 v1(9.8,38.9) ; R20.2@43.5,40.275 v1(44.175,40.275)
Mem_MOSI: CN2.48 U12.5 U13.15 | length 78.8
  Top Layer w0.12: U12.5@32.425,52.92 33.575,52.92 33.975,52.52 33.975,46.786 33.344,46.155 32.569,46.155 32.35,45.936 32.35,44.608 33.238,43.72 39.038,43.72 40.593,42.165 41.921,42.165 42.586,41.5 46.875,41.5 48.85,39.525 51.6,39.525 52.22,38.905 CN2.48@53.5,38.905 54.915,38.905 v1(54.925,38.895) ; U13.15@37.75,18.125 37.75,20.925 38.43,21.605 41.92,21.605 44.665,18.86 49.851,18.86 50.061,18.65 v1(55.825,18.65)
  Bottom Layer w0.12: v1(54.925,38.895) 54.925,38.3 55.01,38.215 55.01,27.91 54.925,27.825 54.925,22.325 55.825,21.425 v1(55.825,18.65)
Mem_NSS: CN1.9 JP3.1 SB37.2 SB38.2 | length 91
  Top Layer w0.12: v1(9.2,58.125) 10.175,58.125 10.7,57.6 11.125,57.6 12.437,58.913 13.687,58.913 14.18,59.405 14.18,62.385 14.83,63.035 CN1.9@16.21,63.035 ; v1(9.321,51.817) 9.375,51.764 9.375,51.75 9.7,51.425 12.275,51.425 12.75,50.95 27.361,50.95 30.201,53.79 33.724,53.79 34.455,53.059 34.455,51.145 34.625,50.975 38.35,50.975 39.825,49.5 40.65,49.5 v1(44.425,45.725) 47.45,45.725 48.655,46.93 48.655,48.18 48.925,48.45 55.364,48.45 56.189,47.625 56.825,47.625 57.12,47.92 57.12,49.499 57.401,49.78 57.405,49.78 57.47,49.845 58.15,49.845 59.62,48.375 63.98,48.375 65.515,46.84
  Top Layer w0.3: 65.515,46.84 JP3.1@67.125,45.23
  Bottom Layer w0.12: v1(9.2,58.125) 9.2,57.592 10.477,56.315 10.477,55.025 9.785,54.333 9.785,52.281 v1(9.321,51.817)
  Bottom Layer w0.3: SB37.2@43.25,47.225 SB38.2@43.25,45.725 v1(44.425,45.725)
MICVDD: C32.2 C87.2 L6.2 U22.19 | length 6.3
  Bottom Layer w0.2: U22.19@39.725,60.075 39.728,60.072 39.728,59.647 39.9,59.475 40.4,59.475 40.75,59.125 40.75,58.825
  Bottom Layer w0.3: C87.2@40.525,58.15 40.525,58.6 40.75,58.825 41.575,58.825 ; C32.2@41.65,58.15 41.65,58.75 41.575,58.825 ; L6.2@43.025,58.175 43.025,58.65 42.85,58.825 41.575,58.825
NetB1_1: B1.1 R3.1 R4.2 | length 4.1
  Top Layer w0.12: R3.1@30.625,4.075 R4.2@30.625,3.2 31.22,3.2 B1.1@33.068,5.048
NetB1_2: B1.2 C13.2 CN2.37 R4.1 R56.2 | length 63.2
  Top Layer w0.12: R56.2@29.65,3.275 C13.2@29.65,2.275 30.6,2.275 R4.1@30.625,2.3 32.3,2.3 B1.2@34.058,4.058 35.075,5.075 v1(35.075,5.1) ; v1(49.075,45.265) 49.085,45.255 CN2.37@50.5,45.255
  Bottom Layer w0.12: v1(35.075,5.1) 36.575,6.6 36.575,7.9 39.51,10.835 46.739,10.835 49.78,13.876 49.78,22.501 51.05,23.771 51.05,27.857 51.795,28.602 51.795,29.198 51.29,29.703 51.29,32.735 49.52,34.505 49.52,35.991 50.055,36.526 50.055,37.8 49.03,38.825 49.03,39.396 47.605,40.821 47.605,42.74 48.595,43.73 48.595,44.785 v1(49.075,45.265)
NetB1_3: B1.3 R2.1 R3.2 | length 18.5
  Top Layer w0.12: R3.2@30.625,4.975 30.625,5.625 31.625,6.625 34.45,6.625 36.065,5.01 ; B1.3@35.048,3.068 36.065,4.085 ; 36.065,4.11 36.065,5.01 ; R2.1@42.85,7.85 42.85,6.725 41.975,5.85 38.8,5.85 38.4,6.25 37.305,6.25 36.065,5.01
NetB1_4: B1.4 R1.1 R2.2 | length 7.5
  Top Layer w0.12: B1.4@37.452,9.432 38.445,10.425 39.8,10.425 40.9,9.325 41.7,9.325 ; R1.1@41.7,8.75 41.7,9.325 ; R2.2@42.85,8.75 42.85,9.2 42.537,9.513 41.887,9.513 41.7,9.325
NetB1_6: B1.6 R1.2 | length 3.5
  Top Layer w0.12: B1.6@39.432,7.452 40.184,6.7 41.25,6.7 41.7,7.15 R1.2@41.7,7.85
NetC5_2: C5.2 C10.2 CN2.31 | length 3.8
  Top Layer w0.3: C5.2@46.725,49.05 C10.2@48.175,49.05 48.19,49.065 CN2.31@50.5,49.065
NetC12_1: C12.1 C16.1 C18.2 R45.2 R51.2 | length 5.9
  Bottom Layer w0.4: C16.1@25.975,66.125 26.825,65.275 R45.2@26.825,63.645 ; R45.2@26.825,63.6 R45.2@26.825,63.645 ; C12.1@29.8,63.675 28.9,63.675 C18.2@28.875,63.7 R51.2@27.875,63.7 26.88,63.7 R45.2@26.825,63.645
NetC17_1: C17.1 U22.10 | length 3
  Top Layer w0.2: v1(41.799,63.535) 41.799,62.876 42.15,62.525 C17.1@42.825,62.525
  Bottom Layer w0.2: U22.10@41.05,63 41.06,63.01 41.661,63.01 41.755,63.104 41.755,63.49 v1(41.799,63.535)
NetC17_2: C17.2 U22.8 | length 2.4
  Top Layer w0.2: v1(41.055,63.945) 41.057,63.943 41.472,63.943 41.584,64.055 42.015,64.055 42.144,63.925 C17.2@42.825,63.925
  Bottom Layer w0.2: U22.8@40.525,63.925 40.534,63.934 41.044,63.934 v1(41.055,63.945)
NetC19_1: C19.1 R54.2 U22.20 | length 3.8
  Top Layer w0.3: v1(39.994,58.846) 40.4,58.439 C19.1@40.4,57.95 R54.2@41.625,57.95
  Bottom Layer w0.12: U22.20@39.325,60.075 39.35,60.05 39.35,59.537 39.575,59.312 39.575,59.3 39.994,58.881 v1(39.994,58.846)
NetC21_1: C21.1 U22.11 | length 2.4
  Bottom Layer w0.2: U22.11@41.05,62.6 41.925,62.6 42.075,62.75 42.075,63.075 42.405,63.405 42.455,63.405 42.675,63.625 C21.1@42.675,63.75
NetC22_1: C22.1 U22.12 | length 1.7
  Bottom Layer w0.2: U22.12@41.05,62.2 42.5,62.2 C22.1@42.675,62.375
NetC23_1: C23.1 U22.27 | length 2.5
  Bottom Layer w0.12: C23.1@35,60.6 35,60.625 35.195,60.82 35.22,60.82 35.8,61.4 U22.27@37.2,61.4
NetC23_2: C23.2 R54.1 SB6.1 SB7.2 | length 54.5
  Top Layer w0.12: v1(22.45,64.425) 22.494,64.469 22.844,64.469 26.615,68.24 30.035,68.24 32.575,65.7 32.575,61.8 32.924,61.451 33.245,61.451 ; v1(33.375,60.6) 33.375,61.321 33.245,61.451 ; v1(44.275,52.175) 42.795,53.655 40.027,53.655 39.297,54.385 36.779,54.385 35.888,55.275 35.888,57.604 34.46,59.032 34.46,61.776 34.106,62.13 33.526,62.13 33.245,61.849 33.245,61.451
  Top Layer w0.3: R54.1@41.625,57.05 42.375,57.05 43.15,57.825 v1(44.475,57.825)
  Bottom Layer w0.12: SB6.1@16.375,62.775 20.8,62.775 v1(22.45,64.425) ; v1(33.375,60.6) C23.2@34.1,60.6 ; v1(44.275,52.175) 43.93,52.52 43.93,53.843 43.505,54.268 43.505,56.48 43.7,56.675 SB7.2@44.475,56.675
  Bottom Layer w0.3: SB7.2@44.475,56.675 v1(44.475,57.825)
NetC24_1: C24.1 C25.1 C88.1 R52.1 R53.2 | length 5.9
  Bottom Layer w0.4: C25.1@25.975,58.625 26.825,59.475 R53.2@26.825,61.105 ; R53.2@26.825,61.15 R53.2@26.825,61.105 ; C88.1@29.8,61.075 28.9,61.075 C24.1@28.875,61.05 R52.1@27.875,61.05 26.88,61.05 R53.2@26.825,61.105
NetC26_1: C26.1 L1.1 U22.13 | length 3.2
  Top Layer w0.4: v1(42.25,61) C26.1@43.175,61
  Bottom Layer w0.2: U22.13@41.05,61.8 41.06,61.79 41.46,61.79 v1(42.25,61)
  Bottom Layer w0.4: v1(42.25,61) L1.1@43.025,61
NetC26_2: C26.2 R49.2 | length 1
  Top Layer w0.4: C26.2@44.075,61 R49.2@45.05,61
NetC27_2: C27.2 U22.21 | length 2.1
  Top Layer w0.3: C27.2@39.15,58.05 39.15,59.025 v1(39.167,59.042)
  Bottom Layer w0.12: U22.21@38.925,60.075 38.925,59.352 39.167,59.11 v1(39.167,59.042)
NetC28_1: C28.1 L3.1 U22.15 | length 3.8
  Top Layer w0.4: v1(42.25,59.625) C28.1@43.175,59.625
  Bottom Layer w0.2: U22.15@41.05,61 41.053,60.997 41.478,60.997 42.25,60.225 v1(42.25,59.625)
  Bottom Layer w0.4: v1(42.25,59.625) L3.1@43.025,59.625
NetC28_2: C28.2 R50.2 | length 1
  Top Layer w0.4: C28.2@44.075,59.625 R50.2@45.05,59.625
NetC29_2: C29.2 CN3.4 L3.2 U5.6 | length 30.1
  Top Layer w0.12: v1(44.925,58.7) 44.925,58.588 45.343,58.17 46.355,58.17 46.604,58.419 46.95,58.765 46.95,59.4 47.45,59.9 54.571,59.9 54.826,59.645 55.224,59.645 56.114,60.535 58.539,60.535 59.575,61.571 59.575,62.963 ; U5.6@57.9,63.2 59.338,63.2 59.575,62.963 ; CN3.4@67.15,64.2 65.4,64.2 64.4,63.2 59.812,63.2 59.575,62.963
  Bottom Layer w0.2: v1(44.925,58.7) C29.2@44.925,59.625
  Bottom Layer w0.4: L3.2@43.975,59.625 C29.2@44.925,59.625
NetC30_2: C30.2 CN3.6 L1.2 U5.4 | length 25.3
  Top Layer w0.12: v1(44.925,61.925) 44.959,61.891 45.33,61.891 45.75,61.471 45.75,60.625 46.07,60.305 47.434,60.305 48.254,61.125 54.545,61.125 54.895,60.775 56.562,60.775 57.087,61.3 U5.4@57.9,61.3
  Top Layer w0.2: U5.4@57.9,61.3 58.625,61.3 v1(59.05,61.725) ; v1(58.2,56.9) 60.15,56.9 CN3.6@60.25,56.8
  Bottom Layer w0.2: C30.2@44.925,61 v1(44.925,61.925) ; v1(58.2,56.9) 59.05,57.75 v1(59.05,61.725)
  Bottom Layer w0.4: L1.2@43.975,61 C30.2@44.925,61
NetC36_2: C36.2 R12.2 TP1.1 | length 3
  Bottom Layer w0.2: R12.2@37.475,45.05 37.419,45.106 37.419,45.431 37.475,45.488 TP1.1@37.475,46.575 ; TP1.1@37.475,46.45 TP1.1@37.475,46.575 ; C36.2@38.75,46.575 TP1.1@37.475,46.575
NetC42_2: C42.2 U6.J14 | length 2.9
  Bottom Layer w0.12: C42.2@34.475,44.15 34.475,43.625 35.2,42.9 35.2,42.025 U6.J14@35.525,41.7
NetC45_2: C45.2 U9.1 | length 1.6
  Bottom Layer w0.12: C45.2@15.4,32.075 15.44,32.035 15.44,31.785 16,31.225 U9.1@16,30.75
NetC48_2: C48.2 U6.M10 | length 7.6
  Bottom Layer w0.12: C48.2@29.65,39.725 30.45,39.725 30.975,39.2 30.975,37.925 31.425,37.475 33.73,37.475 33.925,37.67 33.925,38.75 U6.M10@33.575,39.1
NetC49_2: C49.2 U6.F13 | length 3.5
  Bottom Layer w0.12: U6.F13@37.475,41.05 37.8,41.375 37.8,42.925 38.475,43.6 C49.2@38.475,44.15
NetC59_2: C59.2 D1.2 D2.2 U11.3 U11.5 | length 8.7
  Bottom Layer w0.12: U11.5@41.725,27.525 42.25,27.525 43.575,28.85 U11.3@43.575,29.695
  Bottom Layer w0.6: U11.3@43.575,29.695 C59.2@45.28,29.695 ; C59.2@45.65,29.695 D1.2@47.5,29.695 D2.2@49.37,29.695
NetC70_2: C70.2 R59.1 SB36.1 SB37.1 U12.8 | length 17.8
  Top Layer w0.3: v1(31.625,47.5) 31.647,47.478 32.4,47.478 C70.2@32.4,47.5 32.4,49.085 U12.8@32.425,49.11 ; v1(35.025,47.95) 35.4,48.325 36.25,48.325 36.55,48.025 36.55,46.95 36.775,46.725 37.925,46.725 38.075,46.875 R59.1@38.075,47.525 38.625,47.525 v1(38.975,47.875)
  Bottom Layer w0.3: v1(31.625,47.5) 32.725,47.5 33.175,47.95 v1(35.025,47.95) ; v1(38.975,47.875) 39.825,47.875 40.075,47.625 40.85,47.625 ; 41.9,48.8 41.075,48.8 40.85,48.575 40.85,47.625 ; SB37.1@42.15,47.225 41.25,47.225 40.85,47.625
NetC71_1: C71.1 U13.2 | length 4.1
  Top Layer w0.2: U13.2@28.65,18.125 v1(28.65,20.425)
  Bottom Layer w0.12: C71.1@27.975,18.925 27.975,19.75 v1(28.65,20.425)
NetC71_2: C71.2 U13.1 | length 7
  Top Layer w0.2: U13.1@27.95,18.125 v1(27.95,21.125)
  Bottom Layer w0.12: C71.2@27.625,17.6 27.625,17.625 27.565,17.685 27.54,17.685 27.2,18.025 27.2,19.575 27.95,20.325 v1(27.95,21.125)
NetC72_1: C72.1 U13.3 | length 6.9
  Top Layer w0.2: U13.3@29.35,18.125 v1(29.35,21.125)
  Bottom Layer w0.12: C72.1@29.025,17.625 28.965,17.685 28.65,18 28.65,19.5 29.34,20.19 29.34,21.115 v1(29.35,21.125)
NetC72_2: C72.2 U13.4 | length 4.2
  Top Layer w0.2: U13.4@30.05,18.125 30.075,18.15 v1(30.075,20.425)
  Bottom Layer w0.12: C72.2@29.35,18.825 29.35,19.675 v1@30.1,20.425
